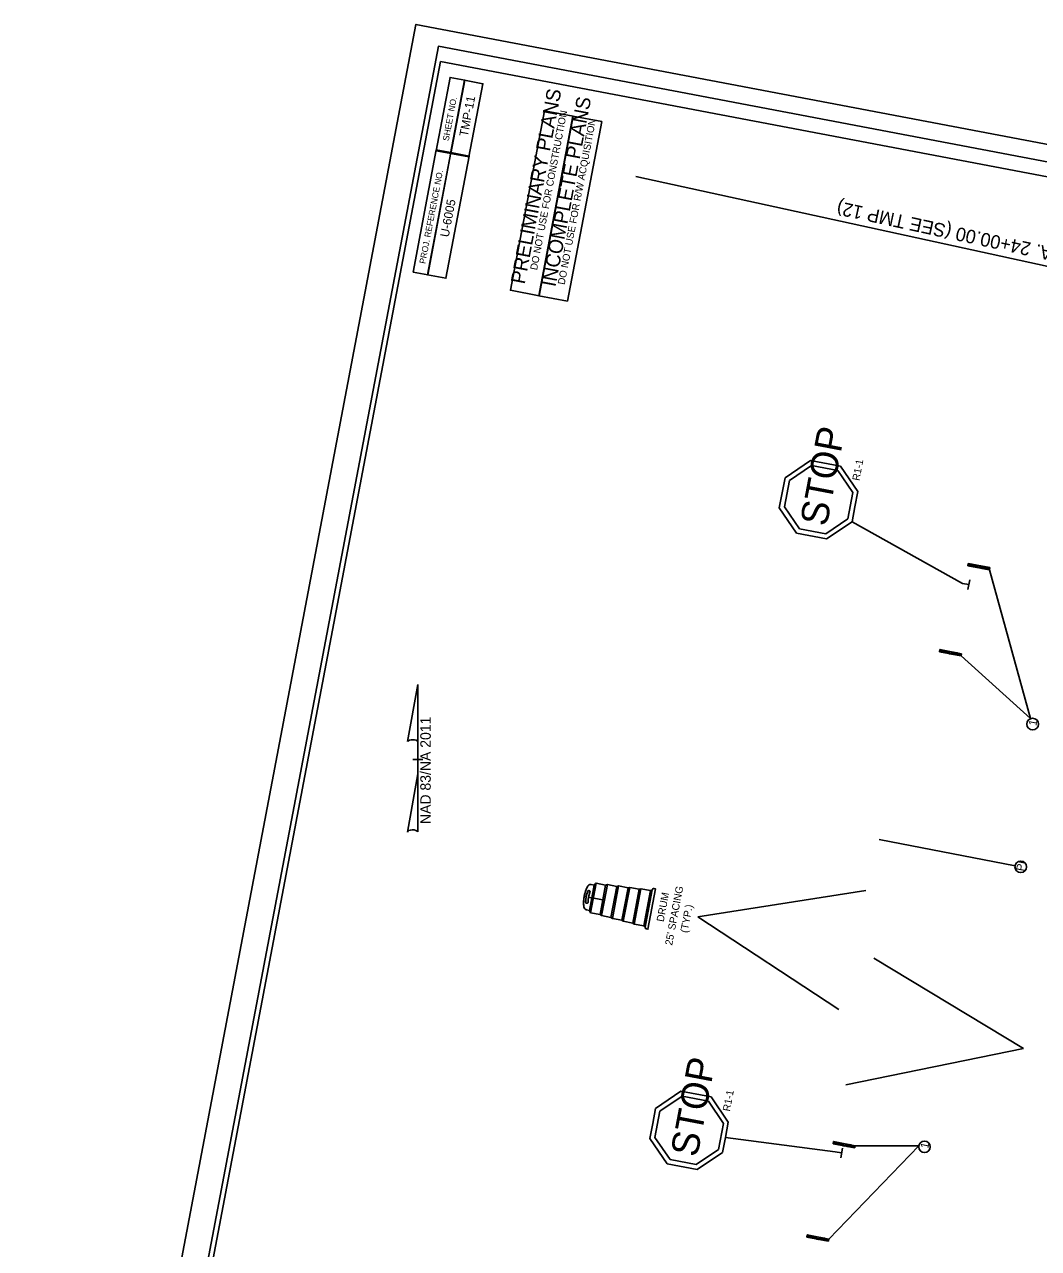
# Model space of a CAD drawing. Extents: x 1615680 to 1619687, y 899305 to 902270.
# Drawn here: x 1618278 to 1619101, y 901276 to 902270 of the extents above; entities that cross this region are included whole.
import ezdxf

# ---------------------------------------------------------------- set-up
doc = ezdxf.new("R2010")
doc.units = 0
for name, color, linetype in [('DEV TYPE 3 BARRICADE CELL', 7, 'Continuous'), ('Exist Roads EOP', 7, 'Continuous'), ('Prop Conc 2ft 9in Curb and Gutter', 7, 'Continuous'), ('Prop EOT', 7, 'Continuous'), ('Prop Lane Arrow CELL', 7, 'Continuous'), ('Prop Mkg Solid Yel Skip RT Rpm 80ft', 7, 'Continuous'), ('Prop Mkg Solid Yellow Edge Line', 7, 'Continuous'), ('Scratch_Level_2', 7, 'Continuous'), ('Scratch_Level_5', 7, 'Continuous'), ('Stage 1', 7, 'Continuous'), ('STAGE 3', 7, 'Continuous'), ('Stage 5', 7, 'Continuous'), ('Stage 6', 7, 'Continuous')]:
    doc.layers.add(name, color=color, linetype=linetype)

msp = doc.modelspace()

# ---------------------------------------------------------------- linework, layer by layer
at = {"layer": 'Exist Roads EOP'}
msp.add_lwpolyline([(1618718.91, 902045.54), (1618695.6, 902049.96), (1618723.28, 902195.76), (1618746.59, 902191.33)], close=True, dxfattribs=at)
at = {"layer": 'Prop Conc 2ft 9in Curb and Gutter'}
for p, q in [((1619044.79, 901815.4), (1619039.63, 901816.38)), ((1619044.03, 901811.39), (1619045.54, 901819.35)), ((1618941.44, 901353.98), (1618936.28, 901354.95)), ((1618940.68, 901349.96), (1618942.19, 901357.92))]:
    msp.add_line(p, q, dxfattribs=at)
at = {"layer": 'Prop EOT'}
for p, q in [((1618899.06, 901899.83), (1618917.1, 901912.06)), ((1618917.1, 901912.06), (1618938.4, 901908.01)), ((1618895.01, 901878.54), (1618899.06, 901899.83)), ((1618938.4, 901908.01), (1618950.63, 901890.04)), ((1618950.63, 901890.04), (1618946.58, 901868.67)), ((1618907.32, 901860.55), (1618895.01, 901878.54)), ((1618928.54, 901856.52), (1618907.32, 901860.55)), ((1618946.58, 901868.67), (1618928.54, 901856.52)), ((1618793.89, 901387.77), (1618811.93, 901399.99)), ((1618811.93, 901399.99), (1618833.23, 901395.95)), ((1618833.23, 901395.95), (1618845.46, 901377.98)), ((1618789.84, 901366.48), (1618793.89, 901387.77)), ((1618845.46, 901377.98), (1618841.41, 901356.61)), ((1618802.15, 901348.49), (1618789.84, 901366.48)), ((1618841.41, 901356.61), (1618823.37, 901344.46)), ((1618823.37, 901344.46), (1618802.15, 901348.49))]:
    msp.add_line(p, q, dxfattribs=at)
at = {"layer": 'Prop Lane Arrow CELL'}
msp.add_line((1618774.33, 902146.68), (1619512.95, 901985.77), dxfattribs=at)
at = {"layer": 'Prop Mkg Solid Yel Skip RT Rpm 80ft'}
for p, q in [((1619039.63, 901816.38), (1618949.89, 901866.44)), ((1619061.58, 901827.38), (1619094.93, 901706.76)), ((1619038.56, 901757.46), (1619094.9, 901706.56)), ((1618972.07, 901608.56), (1619082.28, 901587.13)), ((1618824.8, 901545.53), (1618961.15, 901567.11)), ((1618939.07, 901470.39), (1618824.8, 901545.53)), ((1619089.03, 901438.86), (1618967.61, 901512.07)), ((1618944.79, 901409.2), (1619089.03, 901438.86)), ((1618936.28, 901354.95), (1618847.08, 901366.6)), ((1618931.15, 901283.99), (1619004.18, 901359.75)), ((1618952.48, 901359.77), (1619004.18, 901359.75))]:
    msp.add_line(p, q, dxfattribs=at)
for centre, radius in [((1619096.59, 901702.14), 4.73), ((1619086.92, 901586.25), 4.73), ((1619008.78, 901358.88), 4.68)]:
    msp.add_circle(centre, radius, dxfattribs=at)
at = {"layer": 'Prop Mkg Solid Yellow Edge Line'}
for p, q in [((1618895.53, 901902.18), (1618916.12, 901916.14)), ((1618899.06, 901899.83), (1618917.1, 901912.06)), ((1618916.12, 901916.14), (1618940.58, 901911.49)), ((1618917.1, 901912.06), (1618938.4, 901908.01)), ((1618940.58, 901911.49), (1618954.61, 901890.89)), ((1618893.17, 901889.96), (1618895.53, 901902.18)), ((1618895.01, 901878.54), (1618899.06, 901899.83)), ((1618938.4, 901908.01), (1618950.63, 901890.04)), ((1618890.81, 901877.73), (1618893.17, 901889.96)), ((1618950.63, 901890.04), (1618946.58, 901868.67)), ((1618954.61, 901890.89), (1618952.25, 901878.66)), ((1618904.84, 901857.13), (1618890.81, 901877.73)), ((1618907.32, 901860.55), (1618895.01, 901878.54)), ((1618952.25, 901878.66), (1618949.89, 901866.44)), ((1618928.54, 901856.52), (1618907.32, 901860.55)), ((1618946.58, 901868.67), (1618928.54, 901856.52)), ((1618949.89, 901866.44), (1618929.3, 901852.48)), ((1618929.3, 901852.48), (1618904.84, 901857.13)), ((1618790.36, 901390.12), (1618810.95, 901404.07)), ((1618810.95, 901404.07), (1618835.41, 901399.43)), ((1618793.89, 901387.77), (1618811.93, 901399.99)), ((1618811.93, 901399.99), (1618833.23, 901395.95)), ((1618833.23, 901395.95), (1618845.46, 901377.98)), ((1618835.41, 901399.43), (1618849.44, 901378.82)), ((1618788, 901377.89), (1618790.36, 901390.12)), ((1618789.84, 901366.48), (1618793.89, 901387.77)), ((1618785.64, 901365.67), (1618788, 901377.89)), ((1618845.46, 901377.98), (1618841.41, 901356.61)), ((1618849.44, 901378.82), (1618847.08, 901366.6)), ((1618799.67, 901345.07), (1618785.64, 901365.67)), ((1618802.15, 901348.49), (1618789.84, 901366.48)), ((1618847.08, 901366.6), (1618844.72, 901354.38)), ((1618841.41, 901356.61), (1618823.37, 901344.46)), ((1618844.72, 901354.38), (1618824.14, 901340.42)), ((1618824.14, 901340.42), (1618799.67, 901345.07)), ((1618823.37, 901344.46), (1618802.15, 901348.49))]:
    msp.add_line(p, q, dxfattribs=at)
at = {"layer": 'Scratch_Level_2'}
for p, q in [((1619043.9, 901830.73), (1619044.24, 901832.5)), ((1619043.9, 901830.73), (1619044.24, 901832.5)), ((1619045.98, 901832.17), (1619043.9, 901830.73)), ((1619061.58, 901827.38), (1619043.9, 901830.73)), ((1619044.24, 901832.5), (1619045.98, 901832.17)), ((1619044.24, 901832.5), (1619061.91, 901829.15)), ((1619045.49, 901830.43), (1619047.57, 901831.87)), ((1619047.08, 901830.13), (1619045.49, 901830.43)), ((1619049.16, 901831.57), (1619047.08, 901830.13)), ((1619047.57, 901831.87), (1619049.16, 901831.57)), ((1619048.67, 901829.83), (1619050.75, 901831.27)), ((1619050.26, 901829.52), (1619048.67, 901829.83)), ((1619052.34, 901830.96), (1619050.26, 901829.52)), ((1619050.75, 901831.27), (1619052.34, 901830.96)), ((1619051.85, 901829.22), (1619052.91, 901829.96)), ((1619052.91, 901829.96), (1619053.63, 901828.89)), ((1619055.4, 901830.38), (1619053.81, 901830.69)), ((1619053.81, 901830.69), (1619055.22, 901828.59)), ((1619056.81, 901828.28), (1619055.4, 901830.38)), ((1619058.58, 901829.78), (1619056.99, 901830.08)), ((1619056.99, 901830.08), (1619058.4, 901827.98)), ((1619059.99, 901827.68), (1619058.58, 901829.78)), ((1619061.91, 901829.15), (1619060.17, 901829.48)), ((1619060.17, 901829.48), (1619061.58, 901827.38)), ((1619053.44, 901828.92), (1619051.85, 901829.22)), ((1619052.03, 901829.19), (1619053.63, 901828.89)), ((1619055.22, 901828.59), (1619056.81, 901828.28)), ((1619058.4, 901827.98), (1619059.99, 901827.68)), ((1619061.91, 901829.15), (1619061.58, 901827.38)), ((1619061.58, 901827.38), (1619061.91, 901829.15)), ((1619020.89, 901760.81), (1619021.22, 901762.58)), ((1619020.89, 901760.81), (1619021.22, 901762.58)), ((1619022.96, 901762.25), (1619020.89, 901760.81)), ((1619038.56, 901757.46), (1619020.89, 901760.81)), ((1619021.22, 901762.58), (1619022.96, 901762.25)), ((1619021.22, 901762.58), (1619038.89, 901759.23)), ((1619022.48, 901760.51), (1619024.55, 901761.95)), ((1619024.07, 901760.21), (1619022.48, 901760.51)), ((1619026.14, 901761.65), (1619024.07, 901760.21)), ((1619024.55, 901761.95), (1619026.14, 901761.65)), ((1619025.66, 901759.91), (1619027.73, 901761.35)), ((1619027.25, 901759.6), (1619025.66, 901759.91)), ((1619029.32, 901761.04), (1619027.25, 901759.6)), ((1619027.73, 901761.35), (1619029.32, 901761.04)), ((1619028.84, 901759.3), (1619029.89, 901760.03)), ((1619029.89, 901760.03), (1619030.61, 901758.97)), ((1619032.38, 901760.46), (1619030.79, 901760.76)), ((1619030.79, 901760.76), (1619032.2, 901758.66)), ((1619033.79, 901758.36), (1619032.38, 901760.46)), ((1619035.56, 901759.86), (1619033.97, 901760.16)), ((1619033.97, 901760.16), (1619035.38, 901758.06)), ((1619036.97, 901757.76), (1619035.56, 901759.86)), ((1619030.43, 901759), (1619028.84, 901759.3)), ((1619029.02, 901759.27), (1619030.61, 901758.97)), ((1619032.2, 901758.66), (1619033.79, 901758.36)), ((1619035.38, 901758.06), (1619036.97, 901757.76)), ((1619038.89, 901759.23), (1619037.15, 901759.56)), ((1619037.15, 901759.56), (1619038.56, 901757.46)), ((1619038.89, 901759.23), (1619038.56, 901757.46)), ((1619038.56, 901757.46), (1619038.89, 901759.23)), ((1618934.47, 901361.36), (1618934.81, 901363.13)), ((1618934.47, 901361.36), (1618934.81, 901363.13)), ((1618936.55, 901362.8), (1618934.47, 901361.36)), ((1618934.81, 901363.13), (1618936.55, 901362.8)), ((1618934.81, 901363.13), (1618952.48, 901359.77)), ((1618936.06, 901361.05), (1618938.14, 901362.49)), ((1618938.14, 901362.49), (1618939.73, 901362.19)), ((1618952.14, 901358), (1618934.47, 901361.36)), ((1618937.65, 901360.75), (1618936.06, 901361.05)), ((1618939.73, 901362.19), (1618937.65, 901360.75)), ((1618939.24, 901360.45), (1618941.32, 901361.89)), ((1618940.83, 901360.15), (1618939.24, 901360.45)), ((1618942.91, 901361.59), (1618940.83, 901360.15)), ((1618941.32, 901361.89), (1618942.91, 901361.59)), ((1618942.42, 901359.85), (1618943.48, 901360.58)), ((1618944.01, 901359.54), (1618942.42, 901359.85)), ((1618942.6, 901359.81), (1618944.19, 901359.51)), ((1618943.48, 901360.58), (1618944.19, 901359.51)), ((1618945.97, 901361.01), (1618944.38, 901361.31)), ((1618944.38, 901361.31), (1618945.78, 901359.21)), ((1618945.78, 901359.21), (1618947.37, 901358.91)), ((1618947.37, 901358.91), (1618945.97, 901361.01)), ((1618949.15, 901360.4), (1618947.56, 901360.71)), ((1618947.56, 901360.71), (1618948.96, 901358.6)), ((1618948.96, 901358.6), (1618950.55, 901358.3)), ((1618950.55, 901358.3), (1618949.15, 901360.4)), ((1618952.48, 901359.77), (1618950.74, 901360.1)), ((1618950.74, 901360.1), (1618952.14, 901358)), ((1618952.48, 901359.77), (1618952.14, 901358)), ((1618952.14, 901358), (1618952.48, 901359.77)), ((1618913.15, 901285.58), (1618913.48, 901287.35)), ((1618913.15, 901285.58), (1618913.48, 901287.35)), ((1618915.22, 901287.02), (1618913.15, 901285.58)), ((1618930.82, 901282.22), (1618913.15, 901285.58)), ((1618913.48, 901287.35), (1618915.22, 901287.02)), ((1618913.48, 901287.35), (1618931.15, 901283.99)), ((1618914.74, 901285.28), (1618916.81, 901286.72)), ((1618916.33, 901284.97), (1618914.74, 901285.28)), ((1618918.4, 901286.41), (1618916.33, 901284.97)), ((1618916.81, 901286.72), (1618918.4, 901286.41)), ((1618917.92, 901284.67), (1618919.99, 901286.11)), ((1618919.51, 901284.37), (1618917.92, 901284.67)), ((1618921.58, 901285.81), (1618919.51, 901284.37)), ((1618919.99, 901286.11), (1618921.58, 901285.81)), ((1618921.1, 901284.07), (1618922.15, 901284.8)), ((1618922.69, 901283.77), (1618921.1, 901284.07)), ((1618921.28, 901284.03), (1618922.87, 901283.73)), ((1618922.15, 901284.8), (1618922.87, 901283.73)), ((1618924.64, 901285.23), (1618923.05, 901285.53)), ((1618923.05, 901285.53), (1618924.46, 901283.43)), ((1618924.46, 901283.43), (1618926.05, 901283.13)), ((1618926.05, 901283.13), (1618924.64, 901285.23)), ((1618927.82, 901284.63), (1618926.23, 901284.93)), ((1618926.23, 901284.93), (1618927.64, 901282.83)), ((1618927.64, 901282.83), (1618929.23, 901282.53)), ((1618929.23, 901282.53), (1618927.82, 901284.63)), ((1618931.15, 901283.99), (1618929.41, 901284.32)), ((1618929.41, 901284.32), (1618930.82, 901282.22)), ((1618931.15, 901283.99), (1618930.82, 901282.22)), ((1618930.82, 901282.22), (1618931.15, 901283.99))]:
    msp.add_line(p, q, dxfattribs=at)
at = {"layer": 'Scratch_Level_5'}
for p, q in [((1618736.6, 901550.91), (1618740.5, 901571.44)), ((1618737.55, 901548.93), (1618742.11, 901572.93)), ((1618740.5, 901571.44), (1618738.1, 901571.89)), ((1618742.11, 901572.93), (1618749.81, 901571.47)), ((1618745.25, 901547.47), (1618749.81, 901571.47)), ((1618746.42, 901546.64), (1618751.2, 901571.81)), ((1618749.81, 901571.47), (1618751.2, 901571.81)), ((1618751.2, 901571.81), (1618758.9, 901570.35)), ((1618736.36, 901566.91), (1618736.25, 901566.93)), ((1618754.12, 901545.18), (1618758.9, 901570.35)), ((1618755.29, 901544.36), (1618760.29, 901570.69)), ((1618758.9, 901570.35), (1618760.29, 901570.69)), ((1618760.29, 901570.69), (1618767.99, 901569.22)), ((1618762.99, 901542.9), (1618767.99, 901569.22)), ((1618764.16, 901542.07), (1618769.38, 901569.56)), ((1618767.99, 901569.22), (1618769.38, 901569.56)), ((1618769.38, 901569.56), (1618777.08, 901568.1)), ((1618771.86, 901540.61), (1618777.08, 901568.1)), ((1618773.03, 901539.79), (1618778.47, 901568.44)), ((1618777.08, 901568.1), (1618778.47, 901568.44)), ((1618778.47, 901568.44), (1618786.17, 901566.98)), ((1618780.73, 901538.33), (1618786.17, 901566.98)), ((1618781.87, 901537.33), (1618787.59, 901567.48)), ((1618784.19, 901535.56), (1618790.4, 901568.28)), ((1618786.17, 901566.98), (1618787.56, 901567.31)), ((1618790.4, 901568.28), (1618789.12, 901568.52)), ((1618736.6, 901550.91), (1618734.2, 901551.37)), ((1618734.41, 901556.64), (1618734.3, 901556.67)), ((1618737.55, 901548.93), (1618745.25, 901547.47)), ((1618745.25, 901547.47), (1618746.42, 901546.64)), ((1618746.42, 901546.64), (1618754.12, 901545.18)), ((1618754.12, 901545.18), (1618755.29, 901544.36)), ((1618755.29, 901544.36), (1618762.99, 901542.9)), ((1618762.99, 901542.9), (1618764.16, 901542.07)), ((1618764.16, 901542.07), (1618771.86, 901540.61)), ((1618771.86, 901540.61), (1618773.03, 901539.79)), ((1618773.03, 901539.79), (1618780.73, 901538.33)), ((1618780.73, 901538.33), (1618781.9, 901537.5)), ((1618784.19, 901535.56), (1618782.91, 901535.81))]:
    msp.add_line(p, q, dxfattribs=at)
for points in [[(1618751.2, 901571.81), (1618748.81, 901559.23), (1618735.98, 901561.66), (1618736.19, 901562.74), (1618736.39, 901563.48), (1618736.55, 901564.11), (1618736.72, 901564.65), (1618736.89, 901565.24), (1618737.05, 901565.71), (1618737.11, 901565.95), (1618737.1, 901566.16), (1618737.01, 901566.42), (1618736.86, 901566.63), (1618736.67, 901566.79), (1618736.49, 901566.89), (1618736.25, 901566.93), (1618735.95, 901566.95), (1618735.67, 901566.85), (1618735.51, 901566.74), (1618735.37, 901566.6), (1618735.28, 901566.49), (1618735.22, 901566.33), (1618735.08, 901565.92), (1618734.94, 901565.49), (1618734.81, 901565.06), (1618734.67, 901564.62), (1618734.52, 901564.05), (1618734.36, 901563.44), (1618734.25, 901562.96), (1618734.16, 901562.54), (1618734.06, 901562.03), (1618732.44, 901562.34), (1618732.59, 901563.09), (1618732.73, 901563.67), (1618732.93, 901564.48), (1618733.09, 901565.03), (1618733.27, 901565.64), (1618733.49, 901566.34), (1618733.77, 901567.13), (1618734.08, 901567.91), (1618734.46, 901568.83), (1618734.82, 901569.59), (1618735.14, 901570.24), (1618735.3, 901570.54), (1618735.46, 901570.82), (1618735.67, 901571.08), (1618735.94, 901571.35), (1618736.18, 901571.5), (1618736.48, 901571.69), (1618736.78, 901571.8), (1618737.11, 901571.9), (1618737.4, 901571.94), (1618737.73, 901571.94), (1618737.98, 901571.91), (1618738.1, 901571.89), (1618740.5, 901571.44), (1618740.81, 901571.87), (1618741, 901572.08), (1618741.22, 901572.29), (1618741.47, 901572.52), (1618741.8, 901572.75), (1618741.98, 901572.86), (1618742.11, 901572.93), (1618749.81, 901571.47)], [(1618746.42, 901546.64), (1618748.81, 901559.23), (1618735.98, 901561.66), (1618735.86, 901561.04), (1618735.79, 901560.56), (1618735.72, 901560.07), (1618735.66, 901559.55), (1618735.6, 901558.98), (1618735.55, 901558.4), (1618735.51, 901557.77), (1618735.48, 901557.35), (1618735.4, 901557.13), (1618735.28, 901556.95), (1618735.1, 901556.78), (1618734.92, 901556.7), (1618734.72, 901556.64), (1618734.54, 901556.63), (1618734.19, 901556.69), (1618734.01, 901556.78), (1618733.81, 901556.93), (1618733.67, 901557.13), (1618733.57, 901557.39), (1618733.56, 901557.6), (1618733.59, 901558.07), (1618733.63, 901558.71), (1618733.74, 901560.03), (1618733.87, 901560.96), (1618733.99, 901561.66), (1618734.06, 901562.03), (1618732.44, 901562.34), (1618732.31, 901561.67), (1618732.19, 901560.79), (1618732.07, 901559.91), (1618732, 901558.96), (1618731.95, 901558.05), (1618731.92, 901557.05), (1618731.93, 901555.91), (1618731.96, 901555.23), (1618732.04, 901554.12), (1618732.09, 901553.65), (1618732.14, 901553.35), (1618732.24, 901553.01), (1618732.39, 901552.68), (1618732.65, 901552.3), (1618732.91, 901552.02), (1618733.17, 901551.81), (1618733.47, 901551.62), (1618733.78, 901551.48), (1618734.2, 901551.37), (1618736.6, 901550.91), (1618736.65, 901550.66), (1618736.73, 901550.41), (1618736.87, 901550.05), (1618737.04, 901549.7), (1618737.21, 901549.4), (1618737.55, 901548.93), (1618745.25, 901547.47)], [(1618754.12, 901545.18), (1618758.9, 901570.35), (1618760.29, 901570.69), (1618767.99, 901569.22), (1618769.38, 901569.56), (1618764.16, 901542.07), (1618762.99, 901542.9), (1618755.29, 901544.36)], [(1618771.86, 901540.61), (1618777.08, 901568.1), (1618778.47, 901568.44), (1618786.17, 901566.98), (1618787.56, 901567.31), (1618787.62, 901567.64), (1618787.71, 901567.82), (1618787.85, 901568.05), (1618788.03, 901568.24), (1618788.18, 901568.35), (1618788.4, 901568.46), (1618788.64, 901568.52), (1618788.83, 901568.54), (1618789, 901568.55), (1618789.12, 901568.52), (1618790.4, 901568.28), (1618784.19, 901535.56), (1618782.91, 901535.81), (1618782.73, 901535.85), (1618782.53, 901535.94), (1618782.36, 901536.05), (1618782.21, 901536.18), (1618782.11, 901536.3), (1618781.97, 901536.51), (1618781.9, 901536.74), (1618781.85, 901536.98), (1618781.84, 901537.12), (1618781.87, 901537.33), (1618781.9, 901537.5), (1618780.73, 901538.33), (1618773.03, 901539.79)]]:
    msp.add_lwpolyline(points, close=True, dxfattribs=at)
for centre, radius, start, end in [((1618737.61, 901569.33), 2.61, 79.24937, 152.30015), ((1618744.28, 901568.98), 4.51, 118.73583, 146.94336), ((1618761.4, 901556.84), 29.48, 152.30015, 186.19859), ((1618763.03, 901556.53), 29.48, 160.57536, 177.92338), ((1618736.08, 901566.03), 0.914, 79.24937, 160.57536), ((1618764.95, 901556.16), 29.48, 161.10062, 177.39812), ((1618736.19, 901566.01), 0.914, 341.10062, 79.24937), ((1618788.87, 901567.24), 1.31, 79.24937, 169.24937), ((1618734.69, 901553.93), 2.61, 186.19859, 259.24937), ((1618734.47, 901557.56), 0.914, 177.92338, 259.24937), ((1618734.58, 901557.54), 0.914, 259.24937, 357.39812), ((1618741.02, 901551.82), 4.51, 191.55539, 219.76292), ((1618783.15, 901537.09), 1.31, 169.24937, 259.24937)]:
    msp.add_arc(centre, radius, start, end, dxfattribs=at)
at = {"layer": 'STAGE 3'}
for p, q in [((1618589, 901687.97), (1618597.2, 901734.32)), ((1618597.25, 901734.32), (1618597.2, 901734.32)), ((1618597.25, 901734.32), (1618597.2, 901734.32)), ((1618597.25, 901734.32), (1618597.25, 901686.52)), ((1618597.25, 901661.72), (1618597.25, 901687.92)), ((1618597.25, 901686.52), (1618597.25, 901687.87)), ((1618593.25, 901673.32), (1618593.2, 901673.32)), ((1618596.8, 901673.32), (1618593.25, 901673.32)), ((1618593.3, 901673.32), (1618601.3, 901673.32)), ((1618597.25, 901661.72), (1618588.9, 901614.47)), ((1618597.3, 901614.67), (1618597.25, 901661.72))]:
    msp.add_line(p, q, dxfattribs=at)
for centre, start_param, end_param in [((1618593.14, 901687.47), 0.216388, 2.908219), ((1618593.14, 901614.3), 0.201328, 3.141593)]:
    msp.add_ellipse(centre, major_axis=(4.23, -0.03), ratio=0.461098, start_param=start_param, end_param=end_param, dxfattribs=at)
at = {"layer": 'Stage 5'}
msp.add_lwpolyline([(1618277.81, 900596.04), (1618595.68, 902270.17), (1619686.64, 902063.03), (1619368.77, 900388.9)], close=True, dxfattribs=at)
at = {"layer": 'Stage 6'}
msp.add_line((1618624, 902165.39), (1618635.3, 902224.89), dxfattribs=at)
for points in [[(1618300.12, 900599.5), (1618613.97, 902252.47), (1619660.79, 902053.71), (1619346.95, 900400.74)], [(1618615.64, 902240.02), (1618333.18, 900752.34), (1619374.55, 900554.62), (1619657.01, 902042.3)], [(1618624.05, 902165.38), (1618635.35, 902224.88), (1618623.45, 902227.14), (1618612.15, 902167.64)], [(1618623.93, 902165.4), (1618635.23, 902224.91), (1618650.1, 902222.08), (1618638.8, 902162.58)], [(1618695.82, 902049.92), (1618672.51, 902054.35), (1618700.19, 902200.14), (1618723.5, 902195.71)], [(1618593.46, 902069.2), (1618612.29, 902168.38), (1618624.19, 902166.12), (1618605.36, 902066.94)], [(1618624.07, 902166.15), (1618605.24, 902066.97), (1618620.11, 902064.14), (1618638.94, 902163.32)]]:
    msp.add_lwpolyline(points, close=True, dxfattribs=at)

# ---------------------------------------------------------------- texts
at = {"layer": 'DEV TYPE 3 BARRICADE CELL'}
for s, p in [('DRUM', (1618796.93, 901541.24)), ("25' SPACING", (1618803.81, 901522.13)), ('(TYP.)', (1618816.25, 901532.28))]:
    msp.add_text(s, height=6, rotation=79.24937, dxfattribs=at).set_placement(p)
at = {"layer": 'Exist Roads EOP'}
for s, height, p in [('INCOMPLETE PLANS', 11.6294, (1618708.99, 902056.62)), ('DO NOT USE FOR R/W ACQUISITION', 5.8147, (1618716.49, 902058.53))]:
    msp.add_text(s, height=height, rotation=79.24937, dxfattribs=at).set_placement(p)
at = {"layer": 'Prop Mkg Solid Yel Skip RT Rpm 80ft'}
for s, p in [('1', (1619099.56, 901700.37)), ('PI', (1619089.48, 901582.33)), ('1', (1619011.75, 901357.11))]:
    msp.add_text(s, height=6.5, rotation=79.24937, dxfattribs=at).set_placement(p)
at = {"layer": 'Prop Mkg Solid Yellow Edge Line'}
for s, height, p in [('STOP', 22.161, (1618929.34, 901861.99)), ('R1-1', 6, (1618955.89, 901899.39)), ('STOP', 22.161, (1618824.17, 901349.92)), ('R1-1', 6, (1618850.72, 901387.32))]:
    msp.add_text(s, height=height, rotation=79.24937, dxfattribs=at).set_placement(p)
at = {"layer": 'Stage 1'}
msp.add_text('MATCHLINE -L- STA. 24+00.00 (SEE TMP 12)', height=11, rotation=167.79564, dxfattribs=at).set_placement((1619240.48, 902061.6))
at = {"layer": 'STAGE 3'}
msp.add_text('NAD 83/NA 2011', height=8.5, rotation=90, dxfattribs=at).set_placement((1618607.77, 901621.01))
at = {"layer": 'Stage 6'}
for s, height, rotation, p in [('PRELIMINARY PLANS', 11.6294, 79.24937, (1618684, 902058.84)), ('SHEET NO.', 5.047, 79.24992, (1618622.33, 902175.26)), ('TMP-11', 7, 79.24937, (1618637.74, 902178.71)), ('DO NOT USE FOR CONSTRUCTION', 5.8147, 79.24937, (1618694.11, 902070.39)), ('PROJ. REFERENCE NO.', 5.0467, 79.24992, (1618603.4, 902075.57)), ('U-6005', 7.067, 79.24937, (1618622.29, 902097.07))]:
    msp.add_text(s, height=height, rotation=rotation, dxfattribs=at).set_placement(p)

doc.saveas('drawing.dxf')
